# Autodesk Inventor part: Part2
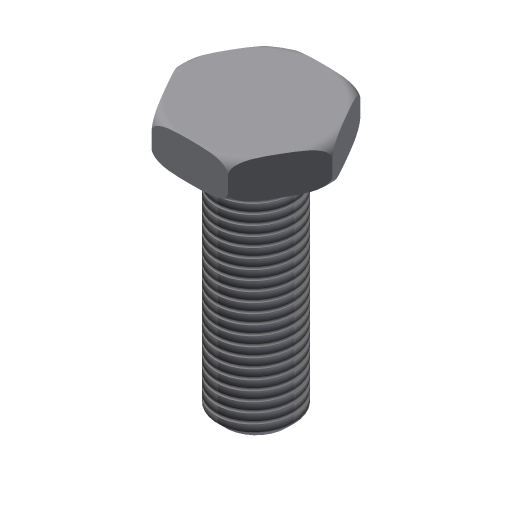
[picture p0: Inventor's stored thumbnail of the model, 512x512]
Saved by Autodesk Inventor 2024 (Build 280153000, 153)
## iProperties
Shininess: 77.0
Angle Display Precision: 2
Document Length Units: 11269
Document Angle Units: 11279
Document Time Units: 11290
Document Mass Units: 11283
Document Length Units Precision: 3
Document Angle Units Precision: 2
Created: 2002-01
Part Number: Part2
Document SubType Name: Modeling
Designer: ***
Density: 1 g/cm^3
Material: Generic
Appearance: Default
Density: 0.0
Volumn: 0.0
Area: 0.0
PropertySet Name: Model Information
Control State: 0
Master: False
Checked Out: False
Author: ***
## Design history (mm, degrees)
sketch "Sketch1"
  geometry: C1 r 20 at (0, 0)
  constraints: 1 centre point
  dimensions: "d0" = 40 diameter of C1
extrude "Extrusion1" new body sketch "Sketch1" distance "d1" = 10; taper "d2" = 0 deg
fillet "Fillet1" dims "d3" = 3
sketch "Sketch3"
  geometry: L1 (20, 0)-(10, -17.321); L2 (10, -17.321)-(-10, -17.321); L3 (-10, -17.321)-(-20, 0); L4 (-20, 0)-(-10, 17.321); L5 (-10, 17.321)-(10, 17.321); L6 (10, 17.321)-(20, 0); C1 r 17 at (0, 0) reference; 1 further point
  constraints: 12 end point, 1 coincident, 11 other
extrude "Extrusion3" sketch "Sketch3" distance "d7" = 10; taper "d8" = 0 deg
sketch "Sketch2"
  geometry: C1 r 10 at (0, 0); 1 further point
  constraints: 1 centre point, 1 coincident
  dimensions: "d4" = 20 diameter of C1
extrude "Extrusion2" join sketch "Sketch2" distance "d5" = 60; taper "d6" = 0 deg
chamfer "Chamfer1" distance "d9" = 2; stored, may be unused: second distance "d10" = 2, angle "d13" = 45 deg
thread "Thread1" dims "d11" = 10, "d12" = 0
body "Solid1"
